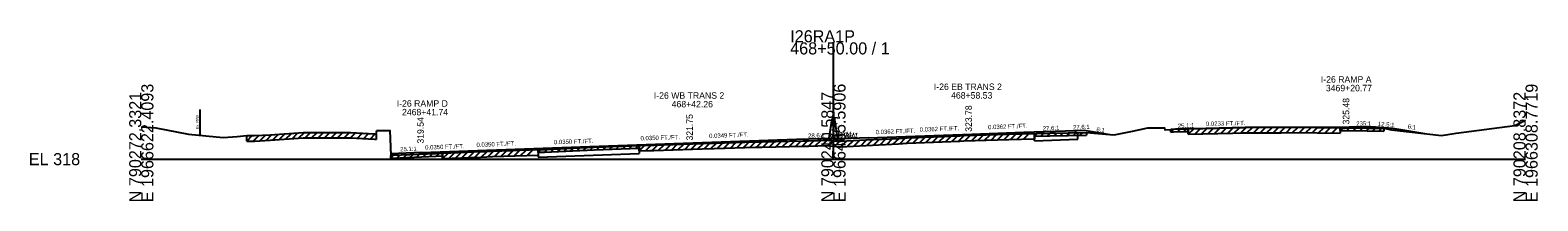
# Model space of a CAD drawing. Extents: x -44 to 4323, y -10 to 9601.
# Drawn here: x 3974.3 to 4322.8, y 6990.3 to 7029.9 of the extents above; entities that cross this region are included whole.
import ezdxf

# ---------------------------------------------------------------- set-up
doc = ezdxf.new("R2010")
doc.units = 0
for name, color, linetype in [('1', 7, 'Continuous'), ('DateStamp', 7, 'Continuous'), ('NotForConst', 7, 'Continuous'), ('QCQA', 7, 'Continuous'), ('RD_SHT_Bndy', 7, 'Continuous'), ('RD_SHT_Iplotshp', 7, 'Continuous'), ('RD_SHT_TX', 7, 'Continuous'), ('RD_XS_ExGround', 7, 'Continuous'), ('RD_XS_MedBWall', 7, 'Continuous'), ('RD_XS_Misc_Line', 7, 'Continuous'), ('RD_XS_Pave', 7, 'Continuous'), ('RD_XS_PaveOvlay', 7, 'Continuous'), ('RD_XS_PaveShd', 7, 'Continuous'), ('RD_XS_TX_Elev_PR', 7, 'Continuous'), ('RD_XS_TX_Profile', 7, 'Continuous'), ('RD_XS_TX_ShdSlope', 7, 'Continuous'), ('RD_XS_TX_Slope', 7, 'Continuous'), ('seal', 7, 'Continuous'), ('TR SN EXTRUDED PANEL SIGNS - GROUND MOUNTED', 7, 'Continuous')]:
    doc.layers.add(name, color=color, linetype=linetype)

msp = doc.modelspace()

# ---------------------------------------------------------------- linework, layer by layer
at = {"layer": 'DateStamp'}
msp.add_lwpolyline([(4000, 7007.45), (4003.39, 7007.26), (4010.89, 7005.78), (4018.91, 7005.02), (4022.17, 7005.23), (4024.37, 7005.45), (4025.81, 7005.45), (4026.19, 7005.45), (4029.77, 7005.65), (4037.39, 7006.16), (4042.56, 7006.2), (4048.36, 7006.16), (4053.88, 7005.84), (4054.32, 7005.82), (4054.43, 7006.62), (4057.05, 7006.62), (4057.44, 7006.62), (4057.68, 7000.87), (4058.05, 7000.88), (4068.13, 7001.3), (4078.38, 7001.74), (4079.85, 7001.8), (4081.19, 7001.85), (4091.91, 7002.2), (4093.2, 7002.26), (4104.67, 7002.78), (4117.58, 7003.24), (4118.51, 7003.27), (4129.65, 7003.63), (4132.46, 7003.72), (4141.94, 7004.01), (4143.49, 7004.04), (4153.04, 7004.23), (4154.21, 7004.26), (4158.52, 7004.38), (4160, 7004.24), (4161.31, 7004.12), (4161.66, 7004.13), (4167.5, 7004.44), (4175.06, 7004.82), (4177.04, 7004.92), (4185.13, 7005.26), (4189.19, 7005.43), (4190.15, 7005.46), (4200.51, 7005.81), (4209.99, 7006.02), (4218.47, 7006.2), (4223.91, 7005.69), (4224.88, 7005.61), (4229.14, 7006.49), (4232.68, 7007.22), (4233.19, 7007.22), (4236.5, 7007.26), (4236.6, 7006.81), (4238.03, 7006.9), (4238.6, 7006.92), (4241.94, 7007.02), (4252.24, 7007.25), (4254.72, 7007.31), (4255.25, 7007.32), (4263.47, 7007.38), (4266.52, 7007.4), (4278.33, 7007.27), (4283.41, 7007.19), (4287.23, 7007.15), (4289.04, 7006.83), (4300.53, 7005.51), (4303.92, 7006.05), (4317.5, 7007.83), (4320, 7009.03)], dxfattribs=at)
at = {"layer": 'NotForConst'}
for p, q in [((4027.37, 7004.26), (4028.69, 7005.59)), ((4028.87, 7004.35), (4030.2, 7005.68)), ((4030.37, 7004.44), (4031.71, 7005.78)), ((4031.87, 7004.54), (4033.21, 7005.88)), ((4033.37, 7004.64), (4034.71, 7005.98)), ((4034.87, 7004.74), (4036.21, 7006.08)), ((4036.37, 7004.84), (4037.69, 7006.16)), ((4037.87, 7004.91), (4039.13, 7006.17)), ((4039.37, 7004.93), (4040.63, 7006.19)), ((4040.87, 7004.94), (4042.13, 7006.2)), ((4042.37, 7004.95), (4043.62, 7006.2)), ((4043.87, 7004.94), (4045.11, 7006.18)), ((4045.37, 7004.93), (4046.61, 7006.17)), ((4046.87, 7004.92), (4048.11, 7006.16)), ((4048.37, 7004.91), (4049.55, 7006.09)), ((4049.87, 7004.82), (4051.06, 7006)), ((4051.37, 7004.73), (4052.56, 7005.92)), ((4052.87, 7004.65), (4054.06, 7005.83)), ((4190.41, 7004.22), (4191.71, 7005.52)), ((4191.91, 7004.27), (4193.21, 7005.57)), ((4193.42, 7004.32), (4194.72, 7005.62)), ((4194.93, 7004.37), (4196.23, 7005.67)), ((4196.43, 7004.42), (4197.73, 7005.72)), ((4197.94, 7004.47), (4199.24, 7005.77)), ((4199.45, 7004.52), (4200.74, 7005.81)), ((4200.95, 7004.57), (4202.24, 7005.85)), ((4202.46, 7004.6), (4203.74, 7005.88)), ((4203.97, 7004.64), (4205.25, 7005.91)), ((4206.47, 7005.32), (4207.11, 7005.95)), ((4207.97, 7005.35), (4208.61, 7005.99)), ((4209.48, 7005.38), (4210.12, 7006.02)), ((4210.98, 7005.42), (4211.62, 7006.05)), ((4212.48, 7005.45), (4213.12, 7006.09)), ((4213.98, 7005.48), (4214.62, 7006.12)), ((4215.48, 7005.51), (4216.12, 7006.15)), ((4216.98, 7005.55), (4217.62, 7006.19)), ((4238.03, 7006.28), (4238.68, 7006.93)), ((4239.53, 7006.33), (4240.18, 7006.97)), ((4241.03, 7006.37), (4241.68, 7007.02)), ((4242.04, 7005.78), (4243.33, 7007.05)), ((4243.55, 7005.81), (4244.83, 7007.09)), ((4245.06, 7005.84), (4246.34, 7007.12)), ((4246.56, 7005.88), (4247.85, 7007.15)), ((4248.07, 7005.91), (4249.35, 7007.19)), ((4249.58, 7005.94), (4250.86, 7007.22)), ((4251.08, 7005.98), (4252.37, 7007.25)), ((4252.59, 7006.01), (4253.87, 7007.29)), ((4254.1, 7006.04), (4255.38, 7007.32)), ((4255.6, 7006.07), (4256.87, 7007.33)), ((4257.11, 7006.08), (4258.37, 7007.34)), ((4258.62, 7006.09), (4259.88, 7007.35)), ((4260.12, 7006.1), (4261.39, 7007.36)), ((4261.63, 7006.11), (4262.89, 7007.37)), ((4263.14, 7006.12), (4264.4, 7007.38)), ((4264.64, 7006.13), (4265.91, 7007.39)), ((4266.15, 7006.14), (4267.4, 7007.39)), ((4267.66, 7006.13), (4268.9, 7007.37)), ((4269.16, 7006.12), (4270.4, 7007.35)), ((4270.67, 7006.1), (4271.91, 7007.34)), ((4272.17, 7006.09), (4273.42, 7007.32)), ((4273.68, 7006.07), (4274.92, 7007.31)), ((4275.19, 7006.05), (4276.43, 7007.29)), ((4277.18, 7006.66), (4277.8, 7007.28)), ((4278.69, 7006.64), (4279.3, 7007.26)), ((4280.19, 7006.62), (4280.8, 7007.23)), ((4281.69, 7006.59), (4282.3, 7007.21)), ((4283.19, 7006.57), (4283.81, 7007.19)), ((4284.69, 7006.55), (4285.31, 7007.17)), ((4286.19, 7006.53), (4286.81, 7007.15)), ((4024.37, 7004.2), (4025.62, 7005.45)), ((4025.87, 7004.2), (4027.17, 7005.5)), ((4086.17, 7000.76), (4087.47, 7002.06)), ((4087.67, 7000.81), (4088.97, 7002.11)), ((4089.18, 7000.86), (4090.48, 7002.16)), ((4091.74, 7001.57), (4092.39, 7002.22)), ((4093.24, 7001.63), (4093.9, 7002.29)), ((4094.75, 7001.7), (4095.4, 7002.36)), ((4096.25, 7001.77), (4096.9, 7002.42)), ((4097.75, 7001.84), (4098.4, 7002.49)), ((4099.25, 7001.91), (4099.91, 7002.56)), ((4100.75, 7001.97), (4101.41, 7002.63)), ((4102.25, 7002.04), (4102.91, 7002.7)), ((4103.75, 7002.11), (4104.41, 7002.76)), ((4105.26, 7002.17), (4105.9, 7002.82)), ((4106.76, 7002.23), (4107.41, 7002.87)), ((4108.26, 7002.28), (4108.91, 7002.93)), ((4109.76, 7002.33), (4110.41, 7002.98)), ((4111.26, 7002.39), (4111.91, 7003.04)), ((4112.76, 7002.44), (4113.41, 7003.09)), ((4114.26, 7002.5), (4114.91, 7003.14)), ((4115.08, 7001.9), (4116.38, 7003.2)), ((4116.58, 7001.95), (4117.89, 7003.25)), ((4118.09, 7002.01), (4119.39, 7003.3)), ((4119.6, 7002.05), (4120.9, 7003.35)), ((4121.1, 7002.1), (4122.4, 7003.39)), ((4122.61, 7002.15), (4123.91, 7003.44)), ((4124.12, 7002.2), (4125.41, 7003.49)), ((4125.62, 7002.25), (4126.92, 7003.54)), ((4127.13, 7002.3), (4128.43, 7003.59)), ((4128.64, 7002.35), (4129.93, 7003.64)), ((4130.14, 7002.39), (4131.44, 7003.68)), ((4131.65, 7002.44), (4132.95, 7003.73)), ((4133.16, 7002.49), (4134.45, 7003.78)), ((4134.66, 7002.53), (4135.96, 7003.82)), ((4136.17, 7002.58), (4137.47, 7003.87)), ((4137.68, 7002.63), (4138.97, 7003.92)), ((4139.18, 7002.67), (4140.48, 7003.96)), ((4140.69, 7002.72), (4141.98, 7004.01)), ((4142.2, 7002.76), (4143.48, 7004.04)), ((4143.7, 7002.79), (4144.98, 7004.07)), ((4145.21, 7002.82), (4146.49, 7004.1)), ((4146.72, 7002.86), (4148, 7004.13)), ((4148.22, 7002.89), (4149.5, 7004.16)), ((4149.73, 7002.92), (4151.01, 7004.19)), ((4151.24, 7002.95), (4152.52, 7004.22)), ((4152.74, 7002.98), (4154.03, 7004.26)), ((4154.25, 7003.01), (4155.54, 7004.3)), ((4155.76, 7003.06), (4157.05, 7004.34)), ((4157.26, 7003.1), (4158.55, 7004.38)), ((4158.77, 7003.11), (4159.91, 7004.25)), ((4160.28, 7002.96), (4161.44, 7004.12)), ((4161.78, 7002.89), (4163.11, 7004.21)), ((4163.29, 7002.97), (4164.61, 7004.29)), ((4164.8, 7003.05), (4166.12, 7004.37)), ((4166.3, 7003.12), (4167.63, 7004.44)), ((4167.81, 7003.2), (4169.13, 7004.52)), ((4169.32, 7003.28), (4170.64, 7004.59)), ((4170.82, 7003.35), (4172.14, 7004.67)), ((4172.33, 7003.43), (4173.65, 7004.75)), ((4173.83, 7003.51), (4175.16, 7004.82)), ((4175.34, 7003.58), (4176.66, 7004.9)), ((4176.85, 7003.66), (4178.16, 7004.96)), ((4178.35, 7003.72), (4179.67, 7005.03)), ((4179.86, 7003.79), (4181.17, 7005.09)), ((4181.37, 7003.85), (4182.68, 7005.16)), ((4182.87, 7003.91), (4184.19, 7005.22)), ((4184.38, 7003.98), (4185.69, 7005.28)), ((4185.89, 7004.04), (4187.2, 7005.35)), ((4187.39, 7004.11), (4188.71, 7005.41)), ((4188.9, 7004.17), (4190.2, 7005.47)), ((4057.68, 7000.25), (4058.33, 7000.9)), ((4059.18, 7000.31), (4059.83, 7000.96)), ((4060.68, 7000.37), (4061.33, 7001.02)), ((4062.18, 7000.43), (4062.83, 7001.08)), ((4063.68, 7000.49), (4064.33, 7001.14)), ((4065.18, 7000.55), (4065.84, 7001.21)), ((4066.68, 7000.62), (4067.34, 7001.27)), ((4068.19, 7000.68), (4068.84, 7001.33)), ((4069.6, 7000.11), (4070.91, 7001.42)), ((4071.1, 7000.18), (4072.41, 7001.48)), ((4072.61, 7000.24), (4073.92, 7001.55)), ((4074.12, 7000.31), (4075.43, 7001.61)), ((4075.62, 7000.37), (4076.93, 7001.68)), ((4077.13, 7000.44), (4078.44, 7001.74)), ((4078.64, 7000.5), (4079.94, 7001.8)), ((4080.14, 7000.56), (4081.45, 7001.86)), ((4081.65, 7000.61), (4082.95, 7001.91)), ((4083.16, 7000.66), (4084.45, 7001.96)), ((4084.66, 7000.71), (4085.96, 7002.01))]:
    msp.add_line(p, q, dxfattribs=at)
at = {"layer": 'QCQA'}
for p, q in [((4190.15, 7005.46), (4200.51, 7005.81)), ((4200.51, 7005.81), (4206.47, 7005.94)), ((4242.04, 7007.03), (4239.1, 7006.93)), ((4242.04, 7007.03), (4252.24, 7007.25)), ((4252.24, 7007.25), (4254.72, 7007.31)), ((4254.72, 7007.31), (4255.25, 7007.32)), ((4255.25, 7007.32), (4263.47, 7007.38)), ((4263.47, 7007.38), (4266.52, 7007.4)), ((4266.52, 7007.4), (4277.18, 7007.28)), ((4277.18, 7007.28), (4285.28, 7007.17)), ((4091.74, 7002.2), (4091.74, 7000.45)), ((4115.08, 7003.15), (4117.58, 7003.24)), ((4115.08, 7003.15), (4115.08, 7001.27)), ((4117.58, 7003.24), (4118.51, 7003.27)), ((4118.51, 7003.27), (4129.65, 7003.63)), ((4129.65, 7003.63), (4132.46, 7003.72)), ((4132.46, 7003.72), (4141.94, 7004.01)), ((4141.94, 7004.01), (4143.49, 7004.04)), ((4143.49, 7004.04), (4153.04, 7004.23)), ((4153.04, 7004.23), (4154.21, 7004.26)), ((4154.21, 7004.26), (4158.52, 7004.38)), ((4158.52, 7004.38), (4160, 7004.24)), ((4160, 7004.24), (4161.31, 7004.12)), ((4161.31, 7004.12), (4161.66, 7004.13)), ((4161.66, 7004.13), (4167.5, 7004.44)), ((4167.5, 7004.44), (4175.06, 7004.82)), ((4175.06, 7004.82), (4177.04, 7004.92)), ((4177.04, 7004.92), (4185.13, 7005.26)), ((4185.13, 7005.26), (4189.19, 7005.43)), ((4189.19, 7005.43), (4190.15, 7005.46))]:
    msp.add_line(p, q, dxfattribs=at)
at = {"layer": 'RD_SHT_Bndy'}
for p, q in [((4160, 7000), (4160, 7027.08)), ((4000, 7000), (4160, 7000)), ((4160, 7000), (4320, 7000))]:
    msp.add_line(p, q, dxfattribs=at)
at = {"layer": 'RD_SHT_Iplotshp'}
for p, q in [((4054.32, 7005.82), (4054.32, 7004.57)), ((4206.47, 7005.94), (4206.47, 7004.69)), ((4206.47, 7005.32), (4206.47, 7005.94)), ((4209.99, 7005.39), (4218.47, 7005.58)), ((4218.47, 7006.2), (4218.47, 7005.58)), ((4238.03, 7006.28), (4238.03, 7006.9)), ((4238.03, 7006.28), (4238.6, 7006.3)), ((4238.6, 7006.3), (4241.94, 7006.4)), ((4241.94, 7006.4), (4242.04, 7006.4)), ((4242.04, 7005.78), (4242.04, 7007.03)), ((4242.04, 7007.03), (4242.04, 7006.4)), ((4242.04, 7005.78), (4252.24, 7006)), ((4252.24, 7006), (4254.72, 7006.06)), ((4254.72, 7006.06), (4255.25, 7006.07)), ((4255.25, 7006.07), (4263.47, 7006.13)), ((4263.47, 7006.13), (4266.52, 7006.15)), ((4266.52, 7006.15), (4277.18, 7006.03)), ((4277.18, 7007.28), (4277.18, 7006.03)), ((4277.18, 7006.66), (4277.18, 7007.28)), ((4277.18, 7006.66), (4278.33, 7006.65)), ((4278.33, 7006.65), (4283.41, 7006.57)), ((4283.41, 7006.57), (4287.23, 7006.52)), ((4287.23, 7007.15), (4287.23, 7006.52)), ((4024.37, 7004.2), (4024.37, 7005.45)), ((4024.37, 7004.2), (4025.81, 7004.2)), ((4025.81, 7004.2), (4026.19, 7004.2)), ((4026.19, 7004.2), (4029.77, 7004.4)), ((4029.77, 7004.4), (4037.39, 7004.91)), ((4037.39, 7004.91), (4042.56, 7004.95)), ((4042.56, 7004.95), (4048.36, 7004.91)), ((4048.36, 7004.91), (4053.88, 7004.59)), ((4053.88, 7004.59), (4054.32, 7004.57)), ((4091.74, 7002.2), (4091.74, 7000.95)), ((4091.74, 7001.57), (4091.74, 7002.2)), ((4093.2, 7001.63), (4104.67, 7002.15)), ((4104.67, 7002.15), (4115.08, 7002.52)), ((4115.08, 7001.9), (4115.08, 7003.15)), ((4115.08, 7003.15), (4115.08, 7002.52)), ((4118.51, 7002.02), (4129.65, 7002.38)), ((4129.65, 7002.38), (4132.46, 7002.47)), ((4132.46, 7002.47), (4141.94, 7002.76)), ((4141.94, 7002.76), (4143.49, 7002.79)), ((4143.49, 7002.79), (4153.04, 7002.98)), ((4153.04, 7002.98), (4154.21, 7003.01)), ((4154.21, 7003.01), (4158.52, 7003.13)), ((4158.52, 7003.13), (4160, 7002.99)), ((4160, 7002.99), (4161.31, 7002.87)), ((4161.31, 7002.87), (4161.66, 7002.88)), ((4161.66, 7002.88), (4167.5, 7003.19)), ((4167.5, 7003.19), (4175.06, 7003.57)), ((4175.06, 7003.57), (4177.04, 7003.67)), ((4177.04, 7003.67), (4185.13, 7004.01)), ((4185.13, 7004.01), (4189.19, 7004.18)), ((4189.19, 7004.18), (4190.15, 7004.21)), ((4190.15, 7004.21), (4200.51, 7004.56)), ((4200.51, 7004.56), (4206.47, 7004.69)), ((4206.47, 7005.32), (4209.99, 7005.39)), ((4057.68, 7000.25), (4057.68, 7000.87)), ((4057.68, 7000.25), (4058.05, 7000.26)), ((4058.05, 7000.26), (4068.13, 7000.68)), ((4068.13, 7000.68), (4069.6, 7000.74)), ((4069.6, 7000.11), (4069.6, 7001.36)), ((4069.6, 7001.36), (4069.6, 7000.74)), ((4069.6, 7000.11), (4078.38, 7000.49)), ((4078.38, 7000.49), (4079.85, 7000.55)), ((4079.85, 7000.55), (4081.19, 7000.6)), ((4081.19, 7000.6), (4091.74, 7000.95)), ((4091.74, 7001.57), (4091.91, 7001.58)), ((4091.91, 7001.58), (4093.2, 7001.63)), ((4115.08, 7001.9), (4117.58, 7001.99)), ((4117.58, 7001.99), (4118.51, 7002.02))]:
    msp.add_line(p, q, dxfattribs=at)
at = {"layer": 'RD_XS_Misc_Line'}
for p, q in [((4206.47, 7004.27), (4206.47, 7005.94)), ((4216, 7006.09), (4216, 7006.65)), ((4216, 7006.09), (4216.5, 7006.11)), ((4216.5, 7004.63), (4216.5, 7006.11)), ((4285.28, 7007.17), (4285.28, 7007.5)), ((4206.47, 7004.27), (4216.5, 7004.63)), ((4091.74, 7000.45), (4115.08, 7001.27))]:
    msp.add_line(p, q, dxfattribs=at)
at = {"layer": 'RD_XS_Pave'}
for p, q in [((4218, 7006.72), (4224.45, 7005.65)), ((4289.29, 7007.18), (4296.75, 7005.95))]:
    msp.add_line(p, q, dxfattribs=at)
at = {"layer": 'RD_XS_PaveOvlay'}
msp.add_line((4013.53, 7011.53), (4013.53, 7005.53), dxfattribs=at)
at = {"layer": 'RD_XS_PaveShd'}
for p, q in [((4216, 7006.65), (4218, 7006.72)), ((4239.1, 7006.93), (4238.03, 7006.9)), ((4285.28, 7007.5), (4289.29, 7007.18))]:
    msp.add_line(p, q, dxfattribs=at)
at = {"layer": 'RD_XS_TX_Elev_PR'}
for p, q in [((4204, 7006.22), (4216, 7006.65)), ((4243.11, 7007.09), (4239.1, 7006.93)), ((4279.25, 7007.48), (4285.28, 7007.5)), ((4151.5, 7004.59), (4160, 7004.88)), ((4168, 7004.91), (4160, 7004.59)), ((4160, 7004.88), (4160, 7004.59)), ((4064.76, 7001.54), (4057.66, 7001.26))]:
    msp.add_line(p, q, dxfattribs=at)
at = {"layer": 'RD_XS_TX_ShdSlope'}
for p, q in [((4159, 7004.85), (4159.67, 7009.38)), ((4160.33, 7009.42), (4159.67, 7009.42)), ((4159.67, 7009.42), (4159.67, 7009.38)), ((4160.33, 7009.09), (4160.33, 7009.42)), ((4161, 7004.63), (4160.33, 7009.09))]:
    msp.add_line(p, q, dxfattribs=at)
at = {"layer": 'RD_XS_TX_Slope'}
for p, q in [((4168, 7004.91), (4192, 7005.78)), ((4192, 7005.78), (4204, 7006.22)), ((4243.11, 7007.09), (4255.15, 7007.38)), ((4255.15, 7007.38), (4279.25, 7007.48)), ((4064.76, 7001.54), (4127.5, 7003.75)), ((4127.5, 7003.75), (4151.5, 7004.59))]:
    msp.add_line(p, q, dxfattribs=at)

# ---------------------------------------------------------------- texts
at = {"layer": '1'}
for s, p in [('I-26 EB TRANS 2', (4183.22, 7016.03)), ('I-26 RAMP A', (4272.68, 7017.73)), ('3469+20.77', (4273.84, 7015.73)), ('I-26 RAMP D', (4059.05, 7012.15)), ('I-26 WB TRANS 2', (4118.49, 7014)), ('468+42.26', (4122.61, 7012)), ('468+58.53', (4187.2, 7014.03)), ('2468+41.74', (4060.27, 7010.15))]:
    msp.add_text(s, height=1.5, dxfattribs=at).set_placement(p)
at = {"layer": 'RD_SHT_Bndy'}
for s, p in [('I26RA1P', (4150, 7027.08)), ('468+50.00 / 1', (4150, 7024.28)), ('EL 318', (3974, 6998.6))]:
    msp.add_text(s, height=2.8, dxfattribs=at).set_placement(p)
for s, p in [('E 1966622.4093', (4002.8, 6990)), ('E 1966465.5906', (4162.8, 6990)), ('E 1966308.7719', (4322.8, 6990)), ('N 790272.3321', (4000, 6990)), ('N 790240.5847', (4160, 6990)), ('N 790208.8372', (4320, 6990))]:
    msp.add_text(s, height=2.8, rotation=90, dxfattribs=at).set_placement(p)
at = {"layer": 'RD_SHT_TX'}
msp.add_text('322.24', height=1, rotation=90, dxfattribs=at).set_placement((4161, 7004.24))
at = {"layer": 'RD_XS_ExGround'}
for s, rotation, p in [('28.6:1', 1.9996, (4154.17, 7004.93)), ('25:1', 2.2906, (4162.94, 7004.96)), ('27.6:1', 2.0728, (4208.41, 7006.63)), ('25.1:1', 2.282, (4059.87, 7001.79))]:
    msp.add_text(s, height=1, rotation=rotation, dxfattribs=at).set_placement(p)
at = {"layer": 'RD_XS_MedBWall'}
for s, rotation, p in [('27.6:1', 2.0728, (4215.41, 7006.88)), ('12.5:1', 355.4437, (4285.83, 7007.71))]:
    msp.add_text(s, height=1, rotation=rotation, dxfattribs=at).set_placement(p)
at = {"layer": 'RD_XS_PaveOvlay'}
msp.add_text('Ex. R/W ', height=0.65, rotation=90, dxfattribs=at).set_placement((4013.28, 7006.91))
at = {"layer": 'RD_XS_TX_Profile'}
for s, p in [('WBW', (4159, 7004.85)), ('EBW', (4161, 7004.63))]:
    msp.add_text(s, height=1.5, dxfattribs=at).set_placement(p)
at = {"layer": 'seal'}
for s, p in [(' 325.48', (4279.25, 7007.48)), ('319.54', (4065.3, 7003.6)), (' 321.75', (4127.5, 7003.75)), (' 323.78', (4192, 7005.78))]:
    msp.add_text(s, height=1.5, rotation=90, dxfattribs=at).set_placement(p)
at = {"layer": 'TR SN EXTRUDED PANEL SIGNS - GROUND MOUNTED'}
for s, rotation, p in [('0.0350 FT./FT.', 2.0054, (4115.42, 7004.32)), ('0.0349 FT./FT.', 1.9996, (4131.28, 7004.88)), ('0.0362 FT./FT.', 2.0728, (4169.78, 7005.77)), ('0.0362 FT./FT.', 2.0728, (4179.96, 7006.35)), ('0.0362 FT./FT.', 2.0728, (4195.77, 7006.92)), ('6:1', 350.5377, (4220.74, 7006.46)), ('25.1:1', 2.2817, (4239.62, 7007.2)), ('0.0233 FT./FT.', 1.3362, (4246.12, 7007.68)), ('235:1', 0.2438, (4280.86, 7007.74)), ('6:1', 350.5737, (4292.69, 7007.13)), ('0.0350 FT./FT.', 2.0054, (4065.63, 7002.2)), ('0.0350 FT./FT.', 2.0054, (4077.5, 7002.82)), ('0.0350 FT./FT.', 2.0054, (4095.4, 7003.44))]:
    msp.add_text(s, height=1, rotation=rotation, dxfattribs=at).set_placement(p)

doc.saveas('drawing.dxf')
